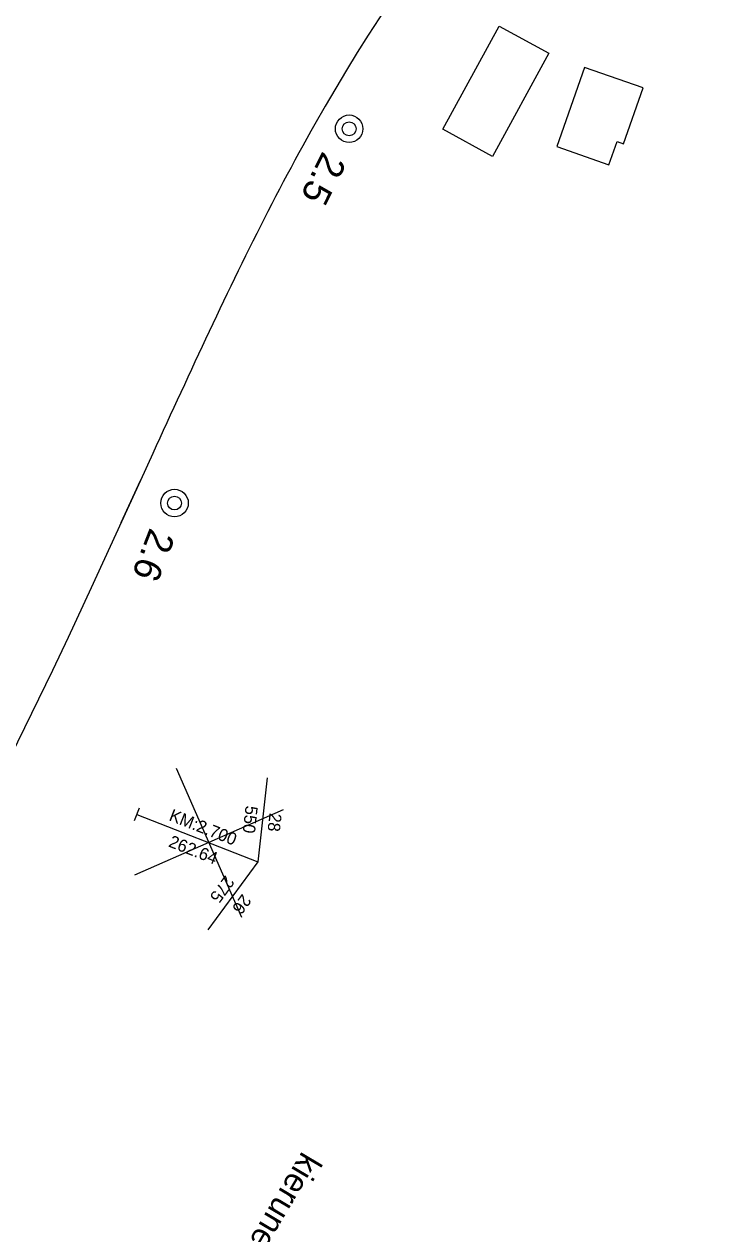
# Model space of a CAD drawing. Extents: x 6541740 to 6566395, y 5525066 to 5530361.
# Drawn here: x 6557675.1 to 6557725.7, y 5526110.1 to 5526198.5 of the extents above; entities that cross this region are included whole.
import ezdxf

# ---------------------------------------------------------------- set-up
doc = ezdxf.new("R2010")
doc.units = 0
for name, color, linetype in [('Domyślna', 7, 'Continuous'), ('ps_wymiarowanie', 7, 'Continuous'), ('TOR_PRZEK_P-komponent', 7, 'Continuous'), ('TOR_PRZEK_P-teren istniejacy', 7, 'Continuous'), ('TOR_PRZEK_P-uklad odniesienia', 7, 'Continuous'), ('TOR_PS_ODW-osadniki', 7, 'Continuous'), ('TOR_PS_OPIS_T-ukresy', 7, 'Continuous'), ('TOR_RAMKI-ramka+tabelka 1', 7, 'Continuous')]:
    doc.layers.add(name, color=color, linetype=linetype)

# ---------------------------------------------------------------- blocks, each defined once
blk = doc.blocks.new('4010_1')
at = {"layer": 'Domyślna'}
for radius in [0.75, 0.375]:
    blk.add_circle((0, 0), radius, dxfattribs=at)

msp = doc.modelspace()

# ---------------------------------------------------------------- linework, layer by layer
at = {"layer": 'ps_wymiarowanie'}
for p, q in [((6557705.726, 5526190.818), (6557709.839, 5526198.36)), ((6557705.726, 5526190.818), (6557709.839, 5526198.36)), ((6557709.839, 5526198.36), (6557713.479, 5526196.375)), ((6557709.839, 5526198.36), (6557713.479, 5526196.375)), ((6557713.479, 5526196.375), (6557709.349, 5526188.821)), ((6557713.479, 5526196.375), (6557709.349, 5526188.821)), ((6557716.082, 5526195.339), (6557714.068, 5526189.558)), ((6557716.082, 5526195.339), (6557714.068, 5526189.558)), ((6557720.373, 5526193.844), (6557716.082, 5526195.339)), ((6557720.373, 5526193.844), (6557716.082, 5526195.339)), ((6557718.951, 5526189.751), (6557720.373, 5526193.844)), ((6557718.951, 5526189.751), (6557720.373, 5526193.844)), ((6557709.349, 5526188.821), (6557705.726, 5526190.818)), ((6557709.349, 5526188.821), (6557705.726, 5526190.818)), ((6557714.068, 5526189.558), (6557717.88, 5526188.227)), ((6557714.068, 5526189.558), (6557717.88, 5526188.227)), ((6557717.88, 5526188.227), (6557718.471, 5526189.919)), ((6557717.88, 5526188.227), (6557718.471, 5526189.919)), ((6557718.471, 5526189.919), (6557718.951, 5526189.751)), ((6557718.471, 5526189.919), (6557718.951, 5526189.751))]:
    msp.add_line(p, q, dxfattribs=at)
at = {"layer": 'TOR_PRZEK_P-komponent'}
msp.add_line((6557684.508, 5526167.104), (6557683.608, 5526165.141), dxfattribs=at)
msp.add_lwpolyline([(6557696.366, 5526191.19), (6557696.072, 5526190.667), (6557695.779, 5526190.143), (6557695.488, 5526189.617), (6557695.199, 5526189.09), (6557694.911, 5526188.561), (6557694.625, 5526188.03), (6557694.34, 5526187.497), (6557694.056, 5526186.963), (6557693.774, 5526186.428), (6557693.494, 5526185.891), (6557693.215, 5526185.353), (6557692.937, 5526184.814), (6557692.66, 5526184.273), (6557692.385, 5526183.731), (6557692.111, 5526183.188), (6557691.838, 5526182.644), (6557691.566, 5526182.098), (6557691.295, 5526181.552), (6557691.025, 5526181.004), (6557690.757, 5526180.456), (6557690.489, 5526179.906), (6557690.222, 5526179.356), (6557689.956, 5526178.805), (6557689.691, 5526178.253), (6557689.427, 5526177.7), (6557689.163, 5526177.147), (6557688.901, 5526176.593), (6557688.639, 5526176.038), (6557688.377, 5526175.482), (6557688.117, 5526174.927), (6557687.856, 5526174.37), (6557687.597, 5526173.813), (6557687.338, 5526173.256), (6557687.079, 5526172.698), (6557686.821, 5526172.139), (6557686.563, 5526171.581), (6557686.305, 5526171.022), (6557686.048, 5526170.463), (6557685.791, 5526169.903), (6557685.534, 5526169.344), (6557685.277, 5526168.784), (6557685.021, 5526168.224), (6557684.764, 5526167.664), (6557684.508, 5526167.104)], dxfattribs=at)
msp.add_ellipse((6557802.903, 5526076.358), major_axis=(-33.081, 171.774), ratio=0.728859, start_param=0.380482, end_param=0.707835, dxfattribs=at)
at = {"layer": 'TOR_PRZEK_P-uklad odniesienia'}
for p, q in [((6557686.221, 5526144.104), (6557690.994, 5526133.224)), ((6557686.221, 5526144.104), (6557690.994, 5526133.224)), ((6557694.048, 5526141.051), (6557683.167, 5526136.277)), ((6557694.048, 5526141.051), (6557683.167, 5526136.277))]:
    msp.add_line(p, q, dxfattribs=at)
at = {"layer": 'TOR_PS_ODW-osadniki'}
for p, q in [((6557683.522, 5526141.194), (6557683.157, 5526140.263)), ((6557683.522, 5526141.194), (6557683.157, 5526140.263)), ((6557683.34, 5526140.729), (6557692.199, 5526137.256)), ((6557683.34, 5526140.729), (6557692.199, 5526137.256))]:
    msp.add_line(p, q, dxfattribs=at)
msp.add_lwpolyline([(6557692.888, 5526143.391), (6557692.199, 5526137.256), (6557688.535, 5526132.288)], dxfattribs=at)
msp.add_lwpolyline([(6557692.888, 5526143.391), (6557692.199, 5526137.256), (6557688.535, 5526132.288)], dxfattribs=at)
at = {"layer": 'TOR_PS_OPIS_T-ukresy'}
msp.add_lwpolyline([(6557682.221, 5526162.114), (6557682.198, 5526162.063), (6557683.608, 5526165.141), (6557680.004, 5526157.293), (6557678.319, 5526153.67), (6557677.177, 5526151.241), (6557673.063, 5526142.852), (6557671.871, 5526140.436), (6557670.736, 5526138.299), (6557669.276, 5526135.625), (6557668.098, 5526133.413), (6557666.781, 5526130.921), (6557665.747, 5526129.034), (6557664.599, 5526126.94), (6557663.773, 5526125.492), (6557662.504, 5526123.254), (6557661.433, 5526121.317), (6557660.187, 5526119.12), (6557658.525, 5526116.092), (6557656.657, 5526112.757), (6557653.288, 5526106.76)], dxfattribs=at)

# ---------------------------------------------------------------- block references
at = {"layer": 'TOR_RAMKI-ramka+tabelka 1'}
for p, xscale, yscale, rotation in [((6557698.874, 5526190.85), 1.345963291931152, 1.3459632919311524, -20.738528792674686), ((6557686.102, 5526163.486), 1.3459632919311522, 1.345963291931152, -15.495757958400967)]:
    msp.add_blockref('4010_1', p, dxfattribs=dict(at, xscale=xscale, yscale=yscale, rotation=rotation))

# ---------------------------------------------------------------- texts
at = {"layer": 'TOR_PRZEK_P-teren istniejacy'}
msp.add_text('kierunek: podg. Bieniowiec --->', height=1.75088, rotation=239.31232, dxfattribs=at).set_placement((6557695.445, 5526116.158))
at = {"layer": 'TOR_PS_ODW-osadniki'}
for s, rotation, p in [('KM:2.700', 338.59592, (6557685.635, 5526140.312)), ('KM:2.700', 338.59592, (6557685.635, 5526140.312)), ('550', 263.59592, (6557691.305, 5526141.394)), ('550', 263.59592, (6557691.305, 5526141.394)), ('28', 263.59592, (6557693.056, 5526140.853)), ('28', 263.59592, (6557693.056, 5526140.853)), ('262.64', 338.59592, (6557685.601, 5526138.393)), ('262.64', 338.59592, (6557685.601, 5526138.393)), ('275', 233.59592, (6557689.83, 5526136.318)), ('275', 233.59592, (6557689.83, 5526136.318)), ('26', 233.59592, (6557691.065, 5526134.96)), ('26', 233.59592, (6557691.065, 5526134.96))]:
    msp.add_text(s, height=0.9, rotation=rotation, dxfattribs=at).set_placement(p)
at = {"layer": 'TOR_RAMKI-ramka+tabelka 1'}
for s, rotation, p in [('2.5', 243.51718, (6557696.945, 5526189.278)), ('2.6', 248.63626, (6557684.319, 5526161.746))]:
    msp.add_text(s, height=2, rotation=rotation, dxfattribs=at).set_placement(p)

doc.saveas('drawing.dxf')
